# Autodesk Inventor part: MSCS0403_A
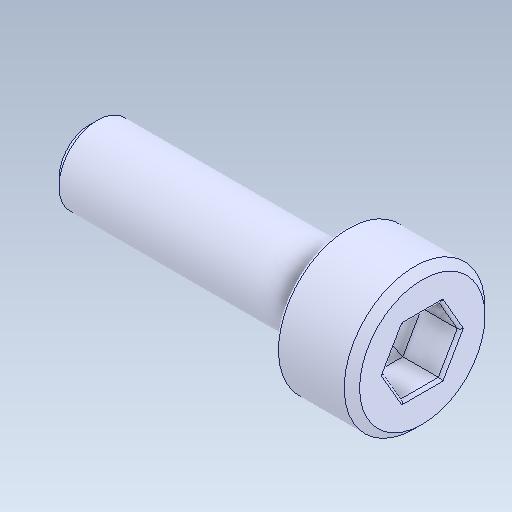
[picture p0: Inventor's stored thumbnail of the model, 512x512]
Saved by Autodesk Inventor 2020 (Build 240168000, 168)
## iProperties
Created: 2017-09
Part Number: MSCS0403_A
Material: Générique
Document SubType Name: Modeling
Designer: bruno
Density: 1 g/cm^3
Appearance: Par défaut
Author: bruno
Sending System: SolidWorks 2016
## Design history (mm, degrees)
feature "Importée1"
node "Solide1"
